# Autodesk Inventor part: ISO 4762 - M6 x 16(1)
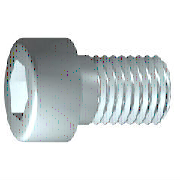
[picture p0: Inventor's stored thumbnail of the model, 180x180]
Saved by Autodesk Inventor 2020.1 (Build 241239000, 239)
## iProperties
Created: 2019-01
Part Number: ISO 4762 - M6 x 16(1)
Material: Edelstahl, 440C
Description: Innensechskantschraube
Document SubType Name: Modeling
Standard: ISO 4762
Designer: lutzd
Standard Revision: Fourth edition 2004-03-01
Standards Organization: ISO
Language: de-DE
Size Designation: M6 x 16
Categories: <MemberInstance><Categories><Category DisplayName="Verbindungselemente" InternalName="e4da775c-781d-43d5-af7c-5136215cf5a6" Mnemonic="FSTN"><Category DisplayNam
Mass: 6.50151 g
Surface Area: 6.88702 cm^2
Volume: 0.838904 cm^3
Density: 7.75 g/cm^3
Appearance: Semi-Polished(3)
IsCustomPart: 0
Author: lutzd
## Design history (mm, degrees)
body "Solid1"
sketch "Skizze1"
  geometry: L1 (-1.333, 0)-(16, 0); L2 (16, 0)-(16, 3); L3 (16, 3)-(2.5, 3); L4 (2.5, 3)-(1.886, 3); L5 (1.886, 3)-(0, 3); L6 (0, 3)-(0, 5); L7 (0, 5)-(-6, 5); L8 (-6, 5)-(-6, 2.887); L9 (-6, 2.887)-(-3, 2.887); L10 (-3, 2.887)-(-1.333, 0); L11 (-10.4, 0)-(20.4, 0) reference; L12 (0, -1)-(0, 6) reference; L13 (2.5, 3)-(0, 3)
  constraints: 22 end point, 6 parallel, 2 collinear, 2 perpendicular, 1 horizontal, 1 point on line
  dimensions: "d1" = 13.5 distance from line of L3.end L2 (= GEL); "d2" = 0.61355 distance of L4.end L3.end (computed from GAL); "d3" = 6 distance between parallel lines of L8 L6 (= KOH); "d4" = 3 distance of L8.end L9.end (= INTI); "d5" = 60 deg angle of L10 L1; "d6" = 6 diameter of L3 L1 (= GD); "d7" = 6 diameter of L5 L1 (= BDM); "d8" = 5.7735 diameter of L9 L1 (= 1.1547 x SW); "d9" = 10 diameter of L7 L1 (= KOD); "d26" = 16 distance between parallel lines of L12 L2 (= NLG)
workplane "Work Plane1"
fillet "Fillet2" dims "d30" = 0.1 (= R)
revolve "Körper" stored, may be unused: angle "d10" = 90 deg
sketch "Skizze2"
  geometry: L1 (0, -7)-(0, 7) reference; L2 (-7, 0)-(7, 0) reference; L3 (2.887, 0)-(1.443, -2.5); L4 (1.443, -2.5)-(-1.443, -2.5); L5 (-1.443, -2.5)-(-2.887, 0); L6 (-2.887, 0)-(-1.443, 2.5); L7 (-1.443, 2.5)-(1.443, 2.5); L8 (1.443, 2.5)-(2.887, 0); 2 further points
  constraints: 12 end point, 1 coincident, 1 horizontal alignment, 1 point on line, 12 other
extrude "Loch" join sketch "Skizze2" stored distance "d11" = 10; taper "d12" = 0 deg
fillet "Rundung1" dims "d17" = 0.6 (= RR)
feature "Gewinde" dims "d13" = 13.5 (= GEL), "d14" = 0
chamfer "Fase1" distance "d15" = 0.61345 (= -0.5 x SPD + 0.5 x GD); stored, may be unused: second distance "d16" = 0.61345 (= GUL), angle "d27" = 45 deg
other parameters: "GD" = 6 [user parameter; used in 2 equation terms], "NLG" = 16 [user parameter; used in 1 equation term], "GEL" = 13.5 [user parameter; used in 2 equation terms], "KOD" = 10 [user parameter; used in 1 equation term], "KOH" = 6 [user parameter; used in 1 equation term], "INTI" = 3 [user parameter; used in 1 equation term], "GAL" = 0.61345 (= 0.61345 x PTC) [user parameter; used in 1 equation term], "GUL" = 0.61345 (= 0.61345 x PTC) [user parameter; used in 1 equation term], "BDM" = 6 (= NND) [user parameter; used in 1 equation term], "SW" = 5 [user parameter; used in 2 equation terms], "RR" = 0.6 [user parameter; used in 1 equation term], "SPD" = 4.7731 (= NND - 1.2269 x PTC) [user parameter; used in 1 equation term], "d19" = 0, "d28" = 0, "d29" = 0, "R" = 0.1 [user parameter; used in 1 equation term], "TOA" = 30 deg [user parameter], "GD1" = 4.7731 (= THREADDIA - 1.2269 x PTC) [user parameter], "THREADDIA" = 6 [user parameter; used in 1 equation term], "FAWI" = 45 deg [user parameter], "PTC" = 1 [user parameter; used in 5 equation terms], "NND" = 6 [user parameter; used in 2 equation terms], "E0" = 5.775 (= 1.155 x SW) [user parameter]
